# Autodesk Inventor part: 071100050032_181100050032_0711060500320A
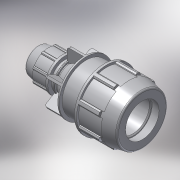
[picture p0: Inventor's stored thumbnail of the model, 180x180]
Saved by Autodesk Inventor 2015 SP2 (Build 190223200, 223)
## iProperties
Created: 2017-02
Part Number: 071100050032_181100050032_0711060500320A
Material: PVC-Piping
Description: PLASSON REDUCING COUPLER 50-32
Document SubType Name: Modeling
Designer: KIM
Mass: 92.6774 g
Surface Area: 199.44 cm^2
Volume: 66.1981 cm^3
Density: 1.4 g/cm^3
Appearance: Smooth - White
Author: KIM
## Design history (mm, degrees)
derived "07110.ipt"
feature "Solid1::07110.ipt"
tag "TaggingFeature1"
body "Solid1"
other parameters: "d4" = 14.58333, "d5" = 25, "d7" = 96, "d9" = 25, "d11" = 2.5, "d12" = 76.8, "d13" = 120 deg, "d14" = 75, "d15" = 12 deg, "d16" = 86.4, "d18" = 2.5, "d19" = 35 deg, "d20" = 17.5 deg, "d21" = 89.28, "d23" = 0, "d25" = 360 deg, "d27" = 1.92, "d42" = 38.5, "d46" = 1.5, "d51" = 175, "d52" = 25, "d53" = 12 deg, "d54" = 98, "d56" = 48, "d57" = 32, "d58" = 45, "d59" = 28.8, "d60" = 57.6, "d61" = 51.2, "d62" = 17.5, "d63" = 28, "d64" = 120 deg, "d65" = 64, "d68" = 12.5, "d74" = 59.52, "d75" = 35 deg, "d76" = 17.5 deg, "d78" = 0, "d80" = 360 deg, "d85" = 1.28, "d88" = 0.64, "d93" = 62, "d94" = 67.2, "d97" = 3.16667, "d98" = 4.26667, "d99" = 0, "d100" = 3.84, "d102" = 360 deg, "d104" = 2, "d106" = 0, "d107" = 4.26667, "d108" = 0, "d109" = 4.26667, "d110" = 0, "E_" = 96, "H_" = 175, "l_" = 98, "d_1" = 32, "E_1" = 64, "l_1" = 62, "d96" = 9.5
